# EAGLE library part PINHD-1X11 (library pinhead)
PIN HEADER
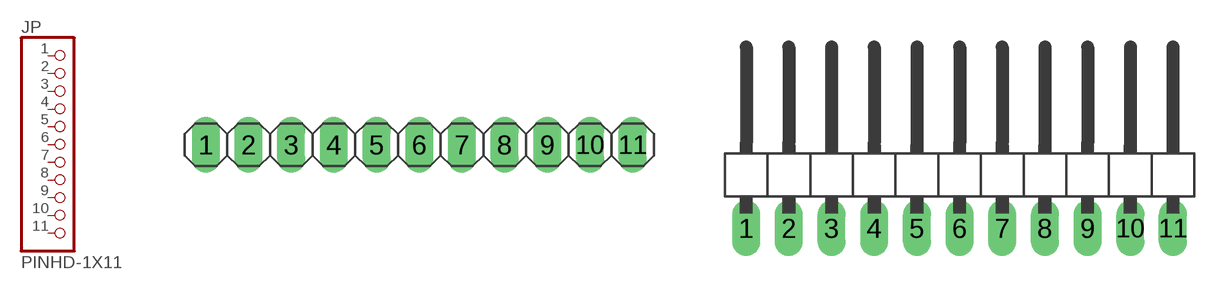
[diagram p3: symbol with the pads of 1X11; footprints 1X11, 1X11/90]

Designator prefix JP

## PINHD-1X11  [1X11]
1  1  pas
2  2  pas
3  3  pas
4  4  pas
5  5  pas
6  6  pas
7  7  pas
8  8  pas
9  9  pas
10  10  pas
11  11  pas

## PINHD-1X11/90  [1X11/90]
Pads as for 1X11

## Footprint 1X11 (pad centres in mm)
PIN HEADER
drill 1.016 pad 1.67 long: 1 -12.7,0; 2 -10.16,0; 3 -7.62,0; 4 -5.08,0; 5 -2.54,0; 6 0,0; 7 2.54,0; 8 5.08,0; 9 7.62,0; 10 10.16,0; 11 12.7,0

## Footprint 1X11/90 (pad centres in mm)
PIN HEADER
drill 1.016 pad 1.67 long: 1 -12.7,-3.81; 2 -10.16,-3.81; 3 -7.62,-3.81; 4 -5.08,-3.81; 5 -2.54,-3.81; 6 0,-3.81; 7 2.54,-3.81; 8 5.08,-3.81; 9 7.62,-3.81; 10 10.16,-3.81; 11 12.7,-3.81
